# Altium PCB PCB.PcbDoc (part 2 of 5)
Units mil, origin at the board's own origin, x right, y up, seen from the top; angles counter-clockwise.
Board outline 6700 x 6500 mil, 2 copper layers (Top Layer, Bottom Layer); 203 components, 278 nets, 1296 pads, 461 vias.
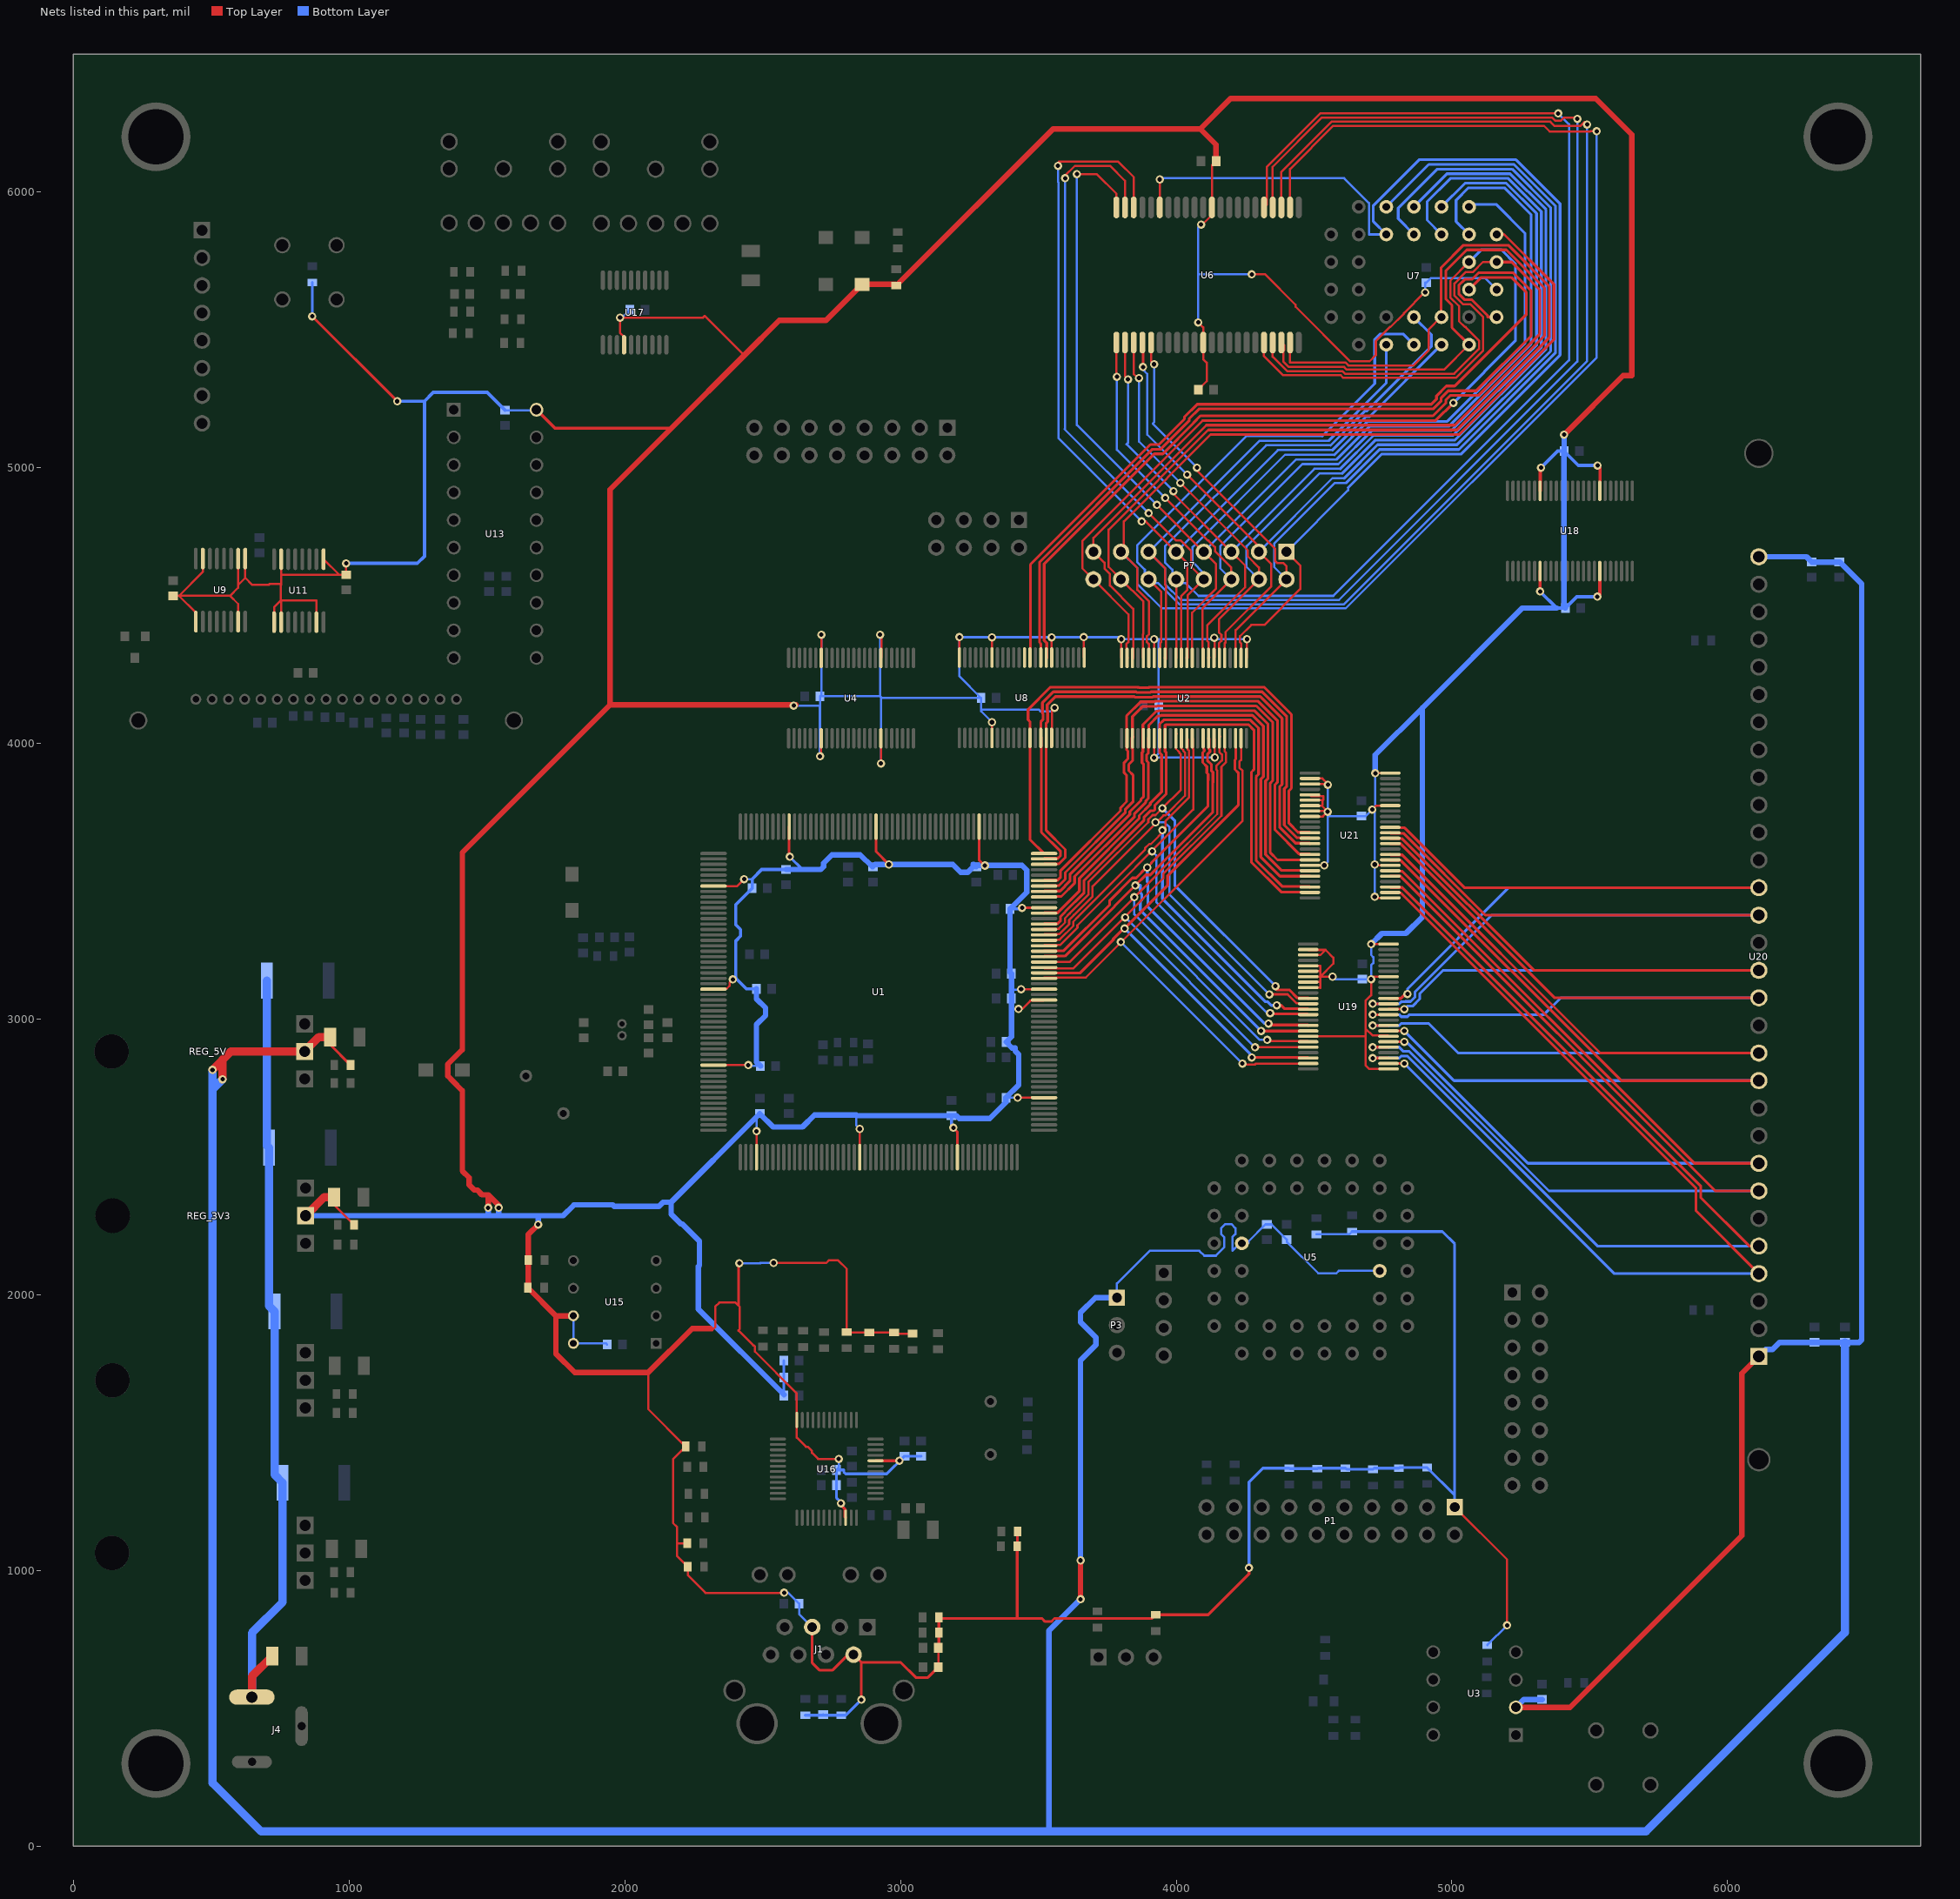
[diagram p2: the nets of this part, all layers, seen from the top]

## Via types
v1: diameter 30, hole 16, Top Layer to Bottom Layer, 461 vias

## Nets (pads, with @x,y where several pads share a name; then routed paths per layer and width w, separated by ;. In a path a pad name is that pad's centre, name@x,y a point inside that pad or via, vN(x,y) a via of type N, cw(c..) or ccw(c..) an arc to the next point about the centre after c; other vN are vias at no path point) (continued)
3V3: C1.1 C2.1 C3.1 C4.1 C6.1 C8.1 C10.1 C12.1 C14.1 C16.1 C18.1 C20.1 C21.1 C24.1 C25.1 C33.1 C34.1 C36.1 C37.1 C38.1 C49.1 C50.1 C51.1 C52.1 C67.1 C68.1 C69.1 C70.1 C76.2 C81.1 C82.1 C85.1 C86.1 C87.1 C88.1 C89.1 C90.1 C91.1 C92.1 C93.1 J1.2 J1.5 L1.2 P1.1 R3.2 R5.2 R7.2 R8.2 R9.2 R10.2 R11.2 R12.2 R15.2 R16.2 R17.2 R18.1 R22.1 R23.1 R27.2 R28.1 R29.1 R30.2 R34.2 R41.2 R42.2 R43.2 R44.2 R45.2 R46.2 R51.2 R59.2 R63.2 REG_3V3.2 U1.7 U1.26 U1.40 U1.56 U1.75 U1.93 U1.111 U1.129 U1.131 U1.146 U1.164 U1.183 U1.199 U2.1 U2.7 U2.18 U2.24 U2.31 U2.42 U4.7 U4.18 U4.31 U4.42 U6.11 U6.33 U7.32 U8.1 U8.7 U8.18 U8.24 U8.31 U8.42 U9.1 U9.2 U9.7 U9.9 U9.15 U11.1 U11.2 U11.7 U11.9 U11.15 U13.20 U15.7 U15.8 U16.22 U16.32 U16.48 U17.14 U18.7 U18.18 U18.31 U18.42 U19.1 U19.7 U19.18 U19.24 U19.26 U19.27 U19.29 U19.30 U19.31 U19.32 U19.33 U19.42 U21.1 U21.7 U21.18 U21.24 U21.26 U21.27 U21.29 U21.30 U21.31 U21.32 U21.33 U21.42 | length 49063.6
  Top Layer w8: C10.1@362,4535.44 383.44,4535.44 ; U9.9@444.43,4441.83 444.43,4474.45 383.44,4535.44 ; U9.7@470.02,4670.17 470.02,4622.02 383.44,4535.44 ; U9.15@597.98,4441.83 597.98,4505.91 568.44,4535.44 ; U9.2@597.98,4670.17 597.98,4575 ; U9.1@623.57,4670.17 623.57,4600.59 ; U11.1@728.43,4439.83 728.43,4493.41 754.02,4519 ; U11.2@754.02,4439.83 754.02,4519 ; U11.15@754.02,4668.17 754.02,4611.98 ; U11.7@881.98,4439.83 881.98,4519 754.02,4519 ; U11.9@907.57,4668.17 964.18,4611.56 ; C76.2@945.85,2354 945.85,2326.68 R51.2@1018.53,2254 ; v1(990,4653) C16.1@990,4611.56 964.18,4611.56 ; R17.2@1648.47,2026 R17.2@1650.47,2028 ; U17.14@1997.59,5445.75 1997.59,5474.41 1983,5489 v1(1983,5544) 2283.88,5544 2290.44,5550.56 2433.5,5407.5 ; 2085,1718 2085,1585.94 R59.2@2220.94,1450 2175,1404.06 2175,1172.53 2190,1157.53 2190,1098 ; R18.1@2226.47,1099 2191,1099 2190,1098 ; 2311,1877.53 2317,1871.53 2328,1882.53 2328,1956.77 2343.23,1972 2401.77,1972 2413,1960.77 ; U1.40@2321.77,2833.07 v1(2447.93,2833.07) ; U1.26@2321.77,3108.66 2324.55,3111.44 2371.1,3111.44 2381,3121.34 2381,3133 v1(2392,3144) ; U1.7@2321.77,3482.68 2407.68,3482.68 v1(2433,3508) ; v1(2416,2115) 2413,2112 2413,1960.77 ; U1.56@2478.27,2499.41 v1(2478.27,2593.73) ; v1(2540,2116) 2731.02,2116 2740.02,2125 2773.98,2125 2805,2093.98 R27.2@2805,1865.53 2807,1863.53 R34.2@2887,1863.53 R30.2@2977,1863.53 2981,1859.53 R23.1@3044,1859.53 ; v1(2578,920) 2577,919 2293,919 2228.47,983.53 R22.1@2228.47,1014 2190,1052.47 2190,1098 ; v1@2612,4138 v1(2613,4137) ; v1(2708,3953) 2708.12,3953 2712.52,3957.4 U4.31@2712.52,4018.66 ; U4.18@2712.52,4310 2713,4310.48 v1(2713,4394) ; v1(2776,1405) 2701.23,1405 2679,1427.23 2679,1433.77 2663.77,1449 2657.23,1449 2624.2,1482.03 U16.48@2624.2,1546 2624.2,1642.22 2472.28,1794.14 2472.28,1812.24 2467.78,1816.75 2466.3,1816.75 2413,1870.05 2413,1871.53 2417,1875.53 2417,1956.77 2413,1960.77 ; U1.75@2852.28,2499.41 v1(2852.28,2601.72) ; v1(2926,4394) 2931.83,4388.17 2931.83,4312.78 U4.7@2929.06,4310 ; v1(2929.06,3927.06) U4.42@2929.06,4018.66 ; C86.1@3137.56,650 C81.1@3137.56,720 ; U8.24@3213.78,4311.34 v1(3213.78,4385.22) ; U8.31@3331.89,4020 v1(3331.89,4076.89) ; U8.18@3331.89,4311.34 v1(3331.89,4385.11) ; v1(3424.96,2714.96) U1.111@3520.59,2714.96 ; v1(3428,3037) 3441.75,3037 3471.27,3066.51 3517.81,3066.51 U1.129@3520.59,3069.29 ; v1(3437.66,3108.66) U1.131@3520.59,3108.66 ; U8.42@3548.43,4020 3550,4021.58 3550,4120 v1(3559,4129) ; U8.7@3548.43,4311.34 v1(3548.43,4384.58) ; v1(3664.78,4385.22) 3664.78,4313.09 U8.1@3666.54,4311.34 ; v1(3801,4378) 3801,4311.21 U2.24@3802.21,4310 ; v1(3920,3948) 3920,4018.35 U2.31@3920.32,4018.66 ; v1(3920,4378) 3920,4310.32 U2.18@3920.32,4310 ; v1(4080,5527) 4098,5509 U6.11@4098,5454 4098,5393.77 4111,5380.77 4111,5313.56 C24.1@4080.44,5283 ; v1(4090,5882) 4095.33,5882 4129.5,5916.16 U6.33@4129.5,5944.08 4129.5,6096.94 C3.1@4144.56,6112 ; U2.42@4136.85,4018.66 4139.63,4015.88 4139.63,3948.63 v1(4140,3949) ; U2.7@4136.85,4310 4139.63,4312.78 4139.63,4381.37 v1(4138,4383) ; U2.1@4254.96,4310 4257,4312.04 v1(4257,4378) ; v1(4274,5701) 4323,5701 4433,5591 4433,5583.79 4630.79,5386 4701.21,5386 4724,5408.79 4724,5458.91 4775.09,5510 4776.91,5510 4826,5559.09 4826,5560.91 4901.18,5636.09 v1(4903,5636.09) ; U19.42@4478.66,2937.52 4686.08,2937.52 4686.6,2937 ; U19.33@4478.66,3114.69 4522.23,3114.69 4523.58,3113.34 4523.58,3135 ; U19.32@4478.66,3134.37 4522.95,3134.37 4523.58,3135 ; U19.31@4478.66,3154.06 4521.52,3154.06 ; U19.30@4478.66,3173.74 4522.32,3173.74 4523.58,3175 ; U19.29@4478.66,3193.43 4523.58,3193.43 4523.58,3175 ; U19.27@4478.66,3232.8 4523.56,3232.8 4541.77,3251 ; U19.26@4478.66,3252.48 4480.14,3251 4541.77,3251 ; U21.42@4485,3557.84 v1(4537.17,3557.84) ; U21.33@4485,3735 4532.12,3735 v1(4549.56,3752.44) v1@4547.32,3754.69 ; U21.32@4485,3754.69 v1@4547.32,3754.69 ; U21.31@4485,3774.37 4527.63,3774.37 ; U21.30@4485,3794.06 4530.95,3794.06 ; U21.29@4485,3813.74 4489.63,3809.11 4533.26,3809.11 4533.26,3796.37 4530.95,3794.06 ; U21.27@4485,3853.11 v1@4549.89,3853.11 ; U21.26@4485,3872.8 4530.21,3872.8 v1@4549.89,3853.11 ; v1(4549.89,3850.11) v1@4549.89,3853.11 ; v1(4566.95,3154.06) 4523.58,3154.06 ; v1(4706.88,3271.88) 4707.17,3272.17 U19.24@4770,3272.17 ; v1(4711,3760) 4725.37,3774.37 U21.18@4776.34,3774.37 ; v1(4720,3444) 4724.28,3439.73 U21.1@4776.34,3439.73 ; v1(4720,3561) 4723.17,3557.84 U21.7@4776.34,3557.84 ; v1(4722,3892) 4722.48,3892.48 U21.24@4776.34,3892.48 ; U19.1@4770,2819.41 4700.59,2819.41 4686.6,2833.4 4686.6,2937 ; U19.7@4770,2937.52 4767.22,2940.3 4712.42,2940.3 4686.6,2966.12 ; U19.18@4770,3154.06 4716.06,3154.06 v1(4706.88,3144.88) 4706.88,3086.68 4686.6,3066.4 4686.6,2966.12 ; P1.1@5010,1230 5200,1040 v1(5200,801.53) ; 383.44,4535.44 568.44,4535.44 ; 568.44,4535.44 597.98,4564.98 597.98,4575 ; 597.98,4575 623.57,4600.59 ; 623.57,4600.59 648.16,4576 709.23,4576 711.23,4578 752.02,4578 754.02,4576 ; 754.02,4519 752,4521.02 752,4573.98 754.02,4576 ; 754.02,4576 754.02,4611.98 ; 754.02,4611.98 754.44,4611.56 964.18,4611.56 ; 4521.52,3154.06 4523.58,3152 ; 4521.52,3154.06 4522.82,3154.06 ; 4522.82,3154.06 4523.58,3154.81 ; 4522.82,3154.06 4523.58,3154.06 ; 4523.58,3135 4523.58,3152 ; 4523.58,3152 4523.58,3154.06 ; 4523.58,3154.06 4523.58,3154.81 ; 4523.58,3154.81 4523.58,3175 ; 4523.58,3154.81 4570,3201.23 4570,3222.77 4541.77,3251 ; 4527.63,3774.37 v1@4547.32,3754.69 ; 4527.63,3774.37 4530.95,3777.69 4530.95,3794.06 ; 4686.6,2937 4686.6,2966.12
  Top Layer w10: v1(867,5549) v1(1175,5241) ; U1.199@2596.38,3698.23 2596.38,3588.62 v1(2598.63,3588.62) ; J1.5@2680,795 2680,665 2706,639 2754,639 2810,695 J1.2@2830,695 2858,667 ; v1(2784,1244) 2784,1237.89 2798.61,1223.28 2798.61,1194.43 U16.22@2801.37,1191.67 ; v1(2858,532) 2858,667 ; U16.32@2909.64,1398.36 v1(2996.36,1398.36) ; U1.183@2911.34,3698.23 2911.34,3607.66 v1(2958,3561) ; C86.1@3137.56,650 3099.56,612 3056,612 3001,667 2858,667 ; C81.1@3137.56,720 3139.53,721.97 R41.2@3139.53,775 R42.2@3139.53,826.22 ; R42.2@3139.53,830 R42.2@3139.53,826.22 ; v1(3192,2606) 3206.61,2591.39 U1.93@3206.61,2499.41 ; U1.164@3285.35,3698.23 3285.35,3576.65 3305,3557 v1(3306,3557) ; R28.1@3424.53,1142 3424.53,1089 R29.1@3423.53,1088 3423.53,826.69 3424,826.22 ; v1(3440.94,3403.94) U1.146@3520.59,3403.94 ; v1(4264,1010) 4264,988 4116,840 R5.2@3926,840 3912.22,826.22 3558.4,826.22 3547.18,815 3524.82,815 3513.6,826.22 3424,826.22 ; R42.2@3139.53,826.22 3424,826.22
  Top Layer w12: U13.20@1680,5210 1747,5143 2169,5143 ; v1(5319.69,4551.32) U18.31@5319.69,4625 ; U18.18@5319.69,4916.34 5320.46,4917.12 5320.46,4997.46 v1(5323,5000) ; v1(5527,4532) 5536.22,4541.22 U18.42@5536.22,4625 ; v1(5528,5008) 5537,4999 5537,4917.12 U18.7@5536.22,4916.34
  Top Layer w20: v1(1505,2316) 1505,2363 ; v1(1543,2316) 1543,2325 1505,2363 ; R17.2@1648.47,2026 1750.47,1924 ; R17.2@1650.47,2028 R16.2@1650.47,2126 1650.47,2219.47 v1(1686,2255) ; U15.7@1814,1924 1750.47,1924 ; 2311,1877.53 2244.53,1877.53 2085,1718 1819,1718 1750.47,1786.53 1750.47,1924 ; v1@2621,4140 1947,4140 ; C3.1@4144.56,6112 4144.56,6171.7 4087.25,6229 ; v1(5407,5120) 5621,5334 5652,5334 5652,6208 5521,6339 4197.25,6339 4087.25,6229 ; 1505,2363 1482.25,2363 1465.25,2380 1454.12,2380 1435.19,2398.93 1435.19,2425.44 1411,2449.62 1411,2740.82 1377.44,2774.38 1377.33,2774.38 1358,2793.71 1358,2836.29 1410.89,2889.18 1411,2889.18 1411,3604 1947,4140 ; 1947,4140 1947,4921 2169,5143 2433.5,5407.5 2560,5534 2729.94,5534 L1.2@2860.94,5665 2980.47,5665 R63.2@2985,5660.47 3553.53,6229 4087.25,6229
  Top Layer w30: REG_3V3.2@843,2287 910,2354 C76.2@945.85,2354
  Bottom Layer w8: C21.1@1566,5208.56 1678.56,5208.56 U13.20@1680,5210 ; 1697,2287 1699,2289 ; U15.7@1814,1924 U15.8@1814,1824 1932.44,1824 C2.1@1936.44,1820 ; v1(1983,5544) 1990.44,5544 C1.1@2018.44,5572 ; v1(2392,3144) 2407.4,3144 2410,3141.4 ; v1(2416,2115) 2492,2115 2491,2116 v1(2540,2116) ; v1(2433,3508) 2462.4,3508 2462.44,3508.04 ; v1(2447.93,2833.07) 2451,2830 C67.1@2492.44,2830 ; v1(2478.27,2593.73) 2478.27,2645.71 C51.1@2490,2657.44 ; v1(2578,920) 2592.56,920 C85.1@2632.56,880 2632.56,842.44 J1.5@2680,795 ; v1(2613,4137) 2708.56,4137 ; v1(2708,3953) 2708,4136.44 2708.56,4137 ; v1(2713,4394) 2713,4175.44 C20.1@2708.56,4171 ; C89.1@2767.56,1365 2776,1373.44 v1(2776,1405) ; 2840,2652.44 2840,2614 v1(2852.28,2601.72) ; v1(2926,4394) 2926,4171 ; v1(2929.06,3927.06) 2929.06,4167.95 ; v1@3331,4386 v1@3331.78,4385.22 ; v1(3331.89,4076.89) 3292.44,4116.34 ; v1(3331.89,4385.11) v1@3331.78,4385.22 ; C34.1@3382.56,2715 C34.1@3382.56,2715 v1(3424.96,2714.96) ; 3402.56,3036 3427,3036 v1(3428,3037) ; 3402.56,3107 3436,3107 v1(3437.66,3108.66) ; v1@3548,4385 v1(3548.43,4384.58) ; v1(3559,4129) 3546.34,4116.34 3507.43,4116.34 3500.77,4123 3299.1,4123 3292.44,4116.34 ; v1(3920,3948) v1@3921,3949 ; v1(4080,5527) 4080,5701 ; v1(4090,5882) 4080,5872 4080,5701 ; v1(4138,4383) v1@4133,4378 ; v1(4140,3949) v1@3921,3949 ; v1(4257,4378) v1@4133,4378 ; v1(4274,5701) 4080,5701 ; R46.2@4509,2219.47 4628,2219.47 R45.2@4638,2229.47 ; v1(4537.17,3557.84) 4549.56,3570.23 4549.56,3736.44 ; v1(4549.89,3850.11) 4549.89,3752.77 v1(4549.56,3752.44) 4549.56,3736.44 ; v1(4566.95,3154.06) 4576.12,3144.88 C33.1@4675,3144.88 v1(4706.88,3144.88) 4706.88,3195.11 4715,3203.23 4715,3224.77 4706.88,3232.89 v1(4706.88,3271.88) ; v1(4720,3444) v1(4720,3561) 4720,3751 v1(4711,3760) ; v1(4722,3892) 4722,3771 v1(4711,3760) ; v1(4903,5636.09) 4903,5671 4903.12,5670.88 C12.1@4907,5670.88 4924.12,5688 5120,5688 U7.32@5162,5646 ; R3.2@5128,729.53 v1(5200,801.53) ; 2708.56,4137 C20.1@2708.56,4171 ; C20.1@2708.56,4171 2926,4171 ; 2926,4171 2929.06,4167.95 ; 2929.06,4167.95 2932,4165 C6.1@3292.44,4165 ; 3292.44,4116.34 C6.1@3292.44,4165 ; C6.1@3292.44,4165 3213.78,4243.66 v1(3213.78,4385.22) v1@3331.78,4385.22 ; v1@3331.78,4385.22 v1(3664.78,4385.22) 3793.78,4385.22 v1(3801,4378) v1(3920,4378) 3936,4378 ; v1@3921,3949 3936.56,3964.56 C38.1@3936.56,4138 3936.56,4377.44 3936,4378 ; 3936,4378 v1@4133,4378 ; 4549.56,3736.44 C18.1@4672,3736.44 4687.44,3736.44 v1(4711,3760)
  Bottom Layer w10: v1(867,5549) R15.2@867,5671.47 ; v1(1175,5241) 1274,5241 ; C87.1@2577.44,1635 2580,1635 2578.72,1636.28 2577.44,1637.56 C88.1@2577.44,1700 C91.1@2577.44,1762 ; v1(2598.63,3588.62) 2644.25,3543 2644.69,3542.56 ; R44.2@2655,475.47 2718.03,475.47 C82.1@2720,477.44 2721.97,475.47 R43.2@2785,475.47 2801.47,475.47 v1(2858,532) ; v1(2784,1244) 2784,1248.18 2767.56,1264.62 C90.1@2767.56,1310 C89.1@2767.56,1365 2794.28,1365 2794.28,1357.72 2801.31,1350.69 2950.69,1350.69 C93.1@3014.88,1414.88 ; v1@2958,3559 v1(2958,3561) ; v1(2996.36,1398.36) 3012.88,1414.88 C93.1@3014.88,1414.88 ; C93.1@3015,1414.88 C93.1@3014.88,1414.88 ; C92.1@3075,1414.88 3074.88,1415 3015,1415 C93.1@3014.88,1414.88 ; C25.1@3185,2649.88 3185,2613 v1(3192,2606) ; C8.1@3397.56,3400 3437,3400 v1(3440.94,3403.94) ; v1(4264,1010) 4264,1321 4314.53,1371.53 R7.2@4410,1371.53 4412,1369.53 R8.2@4512,1369.53 4514,1371.53 R9.2@4614,1371.53 4618,1367.53 R10.2@4714,1367.53 4718,1371.53 R11.2@4808,1371.53 4810,1373.53 R12.2@4910,1373.53 5010,1273.53 ; R45.2@4638,2229.47 4965.53,2229.47 5010,2185 5010,1273.53 ; P1.1@5010,1230 5010,1273.53
  Bottom Layer w12: v1(990,4653) 1248,4653 1274,4679 1274,5241 1306,5273 1501.56,5273 C21.1@1566,5208.56 ; 2407.4,3144 2403,3148.4 2403,3284.4 2420,3301.4 2420,3324.6 2403,3341.6 2403,3415.56 C68.1@2462.44,3475 2462.44,3508.04 2496.96,3542.56 C69.1@2585,3542.56 ; 2410,3141.4 2441.4,3110 C52.1@2477.44,3110 ; v1(5319.69,4551.32) 5380,4491 C14.1@5411.44,4491 5452.44,4532 v1(5527,4532) ; v1(5323,5000) 5383,5060 C50.1@5406.44,5060 5458.44,5008 v1(5528,5008)
  Bottom Layer w20: REG_3V3.2@843,2287 1505,2287 ; v1(1505,2316) 1505,2287 ; v1(1543,2316) 1543,2287 ; v1(1686,2255) 1686,2287 ; C52.1@2477.44,3110 2477.44,3073.81 2511,3040.25 2511,3013.75 2477.44,2980.19 2477.44,2845 C67.1@2492.44,2830 ; C51.1@2478.27,2645.71 2168.56,2336 ; C51.1@2490,2657.44 2538.44,2609 2645,2609 2688.44,2652.44 2705.3,2652.44 2705.75,2652 2839.56,2652 2840,2652.44 2842.56,2649.88 C25.1@3185,2649.88 3202.46,2649.88 3213.05,2639.3 3324.3,2639.3 3382.56,2697.56 C34.1@3382.56,2715 3429,2761.44 3429,2871.56 3416.31,2884.25 3416.31,2895.72 3404.84,2895.72 C37.1@3383.56,2917 3402.56,2936 3402.56,3036 C4.1@3402.56,3075 3402.56,3107 C36.1@3402.56,3165 3397.56,3170 C8.1@3397.56,3400 3458,3460.44 3458,3540 3440.28,3557.72 3275,3557.72 C49.1@3275,3552.56 3266.56,3561 3263,3561 3263,3551.75 3244.25,3533 3217.75,3533 3189.75,3561 v1(2958,3561) 2908.44,3561 C70.1@2900,3552.56 2897.61,3552.56 2854.17,3596 2751.75,3596 2721,3565.25 2721,3553 2710.56,3542.56 2644.69,3542.56 ; C87.1@2577.44,1637.56 2271.06,1943.94 2267,1948 2267,2103.25 2271.06,2107.31 2271.06,2195.23 2208.97,2257.31 2204.38,2257.31 2168.56,2293.14 2168.56,2336 ; C69.1@2585,3542.56 2585.44,3543 2644.25,3543 ; v1(4706.88,3271.88) 4746,3311 4833,3311 4893,3371 4893,4129 ; v1(4722,3892) 4722,3958 4893,4129 ; 5380,4491 5255,4491 4893,4129 ; v1(5407,5120) 5407,5060.56 C50.1@5406.44,5060 5406.44,4496 C14.1@5411.44,4491 ; 1505,2287 1543,2287 ; 1543,2287 1686,2287 ; 1686,2287 1697,2287 1777,2287 1816.33,2326.33 1956.25,2326.33 1961.58,2321 2124.18,2321 2139.18,2336 2168.56,2336
5V: C32.1 C56.1 C57.1 C74.2 C75.1 C77.1 C83.1 C84.1 P3.1 R49.2 REG_5V.2 U3.2 U5.12 U5.34 U20.1 U20.30 | length 19589
  Top Layer w10: C74.2@931.85,2935 931.85,2907.68 R49.2@1005.53,2834
  Top Layer w20: v1(3653,896) v1(3653,1037) ; U3.2@5232,504 5428,504 6051,1127 6051,1715 U20.1@6113,1777
  Top Layer w30: v1(505,2816) 572,2883 REG_5V.2@839,2883 891,2935 C74.2@931.85,2935 ; v1(542,2782) 542,2845
  Bottom Layer w8: P3.1@3785,1990 3785,2041 3904,2160 4084.21,2160 4102.21,2142 4143.91,2142 4174,2172.09 4174,2209.23 4163,2220.23 4163,2241.77 4178.23,2257 4199.77,2257 4215,2241.77 4215,2220.23 4204,2209.23 4204,2160 4231,2187 U5.34@4238,2187 4260.44,2187 4263,2189.56 4263,2194.77 4323.79,2255.56 C57.1@4329,2255.56 4345.88,2255.56 C56.1@4401,2200.44 4401,2192.23 4515.23,2078 4580.77,2078 4589.77,2087 U5.12@4738,2087
  Bottom Layer w20: 3539,54 3539,782 v1(3653,896) ; v1(3653,1037) 3653,1762.75 3709,1818.75 3709,1845.25 3653,1901.25 3653,1936 3707,1990 P3.1@3785,1990 ; U3.2@5232,504 5260.44,532.44 C32.1@5327,532.44 ; U20.1@6113,1777 6138,1802 6162.56,1802 6188,1827.44 C84.1@6315,1827.44 C77.1@6425,1827.44 6476.44,1827.44 6486,1837 6486,4578.95 6407.39,4657.56 C75.1@6405,4657.56 C83.1@6305,4657.56 6285.56,4677 U20.30@6113,4677
  Bottom Layer w30: v1(505,2816) 505,2745 ; v1(542,2782) 505,2745 ; C77.1@6425,1827.44 6425,775 5704,54 3539,54 681,54 505,230 505,2745
12V: C71.2 J4.VCC R58.1 R60.2 R61.2 R62.2 | length 2848.1
  Top Layer w30: J4.VCC@648,541 648,616.15 C71.2@721.85,690
  Bottom Layer w30: J4.VCC@648,541 648,774 758.8,884.8 R58.1@758.8,1319 729.8,1348 R62.2@729.8,1940 709.8,1960 R61.2@709.8,2534 701.8,2542 R60.2@701.8,3140
A_3V3_BUF_0: P7.1 U2.2 U6.39 U7.12 | length 4380.6
  Top Layer w8: U6.39@3940.52,5944.08 v1(3940.52,6045.52) ; U2.2@4235.28,4310 4235.28,4362.96 4231,4367.23 4231,4388.77 4272.23,4430 4320,4430 4450,4560 4450,4645 P7.1@4400,4695
  Bottom Layer w8: v1(3940.52,6045.52) 3945,6050 4608.91,6050 4699,5959.91 4699,5846 U7.12@4762,5846 ; P7.1@4400,4695 4623.42,4918.42 4623.42,4928
  Bottom Layer w10: 4623.42,4928 4744.42,5049 5032.29,5049 5392,5408.71 5392,5957.25 5232.25,6117 4880.67,6117 4715,5951.33 4715,5893 U7.12@4762,5846
A_3V3_BUF_1: P7.2 U2.3 U6.5 U7.11 | length 4168.6
  Top Layer w8: U6.5@3909.02,5454 3909.02,5385.98 v1(3920,5375) ; v1(4075,5000) 4075,4990 4359.47,4705.53 4359.47,4660.92 4365.92,4654.47 4387.94,4654.47 4400,4642.42 P7.2@4400,4595 4215.59,4410.59 U2.3@4215.59,4310
  Bottom Layer w8: v1(3920,5375) 3920,5165 3915,5160 v1(4075,5000) ; P7.2@4400,4595 4355,4640 4355,4724.61 4575.39,4945 4616.37,4945
  Bottom Layer w10: 4616.37,4945 4737.37,5066 5025.25,5066 5375,5415.75 5375,5950.21 5225.21,6100 4916,6100 U7.11@4762,5946
A_3V3_BUF_2: P7.3 U2.5 U6.4 U7.10 | length 4075.9
  Top Layer w8: U6.4@3877.53,5454 3880,5451.53 v1(3880,5365) ; v1(4040,4975) 4300,4715 P7.3@4300,4695 4345,4650 4345,4570 4179,4404 4179,4366.02 4176.22,4363.24 U2.5@4176.22,4310
  Bottom Layer w8: v1(3880,5365) 3880,5355 3895,5340 3895,5120 v1(4040,4975) ; P7.3@4300,4695 4567,4962 4609.33,4962
  Bottom Layer w10: 4609.33,4962 4730.33,5083 5018.21,5083 5358,5422.79 5358,5943.17 5218.17,6083 4946.67,6083 4805,5941.33 4805,5903 U7.10@4862,5846
A_3V3_BUF_3: P7.4 U2.6 U6.3 U7.9 | length 4019.7
  Top Layer w8: U6.3@3846.03,5454 3846.03,5338.97 3865,5320 v1(3865,5325) ; v1(4015,4945) 4259.47,4700.53 4259.47,4678.21 4300,4637.69 P7.4@4300,4595 4155,4450 4155,4402.77 4164,4393.77 4164,4372.23 4155,4363.23 4155,4311.54 U2.6@4156.54,4310
  Bottom Layer w8: v1(3865,5325) 3865,5095 v1(4015,4945) ; P7.4@4300,4595 4255,4640 4255,4715 4519,4979 4602.29,4979
  Bottom Layer w10: 4602.29,4979 4723.29,5100 5011.17,5100 5341,5429.83 5341,5936.12 5211.12,6066 4981.96,6066 U7.9@4862,5946
A_3V3_BUF_4: P7.5 U2.8 U6.2 U7.8 | length 3952.8
  Top Layer w8: U6.2@3814.54,5454 3814.54,5330.46 v1(3825,5320) ; v1(3990,4915) 3990,4905 P7.5@4200,4695 4250,4645 4250,4566.21 4112,4428.21 4112,4372.23 4117.17,4367.07 U2.8@4117.17,4310
  Top Layer w10: U2.8@4117.17,4310 U2.8@4118.94,4311.78
  Bottom Layer w8: v1(3825,5320) 3825,5090 3820,5085 v1(3990,4915) ; P7.5@4200,4695 4501,4996 4595.25,4996
  Bottom Layer w10: 4595.25,4996 4716.25,5117 5004.12,5117 5324,5436.88 5324,5929.08 5204.08,6049 4994,6049 4910,5965 4910,5898 U7.8@4962,5846
A_3V3_BUF_5: P7.6 U2.9 U6.1 U7.7 | length 3852.2
  Top Layer w8: U6.1@3783.04,5454 3783.04,5331.96 v1(3785,5330) ; v1(3960,4890) 4114.47,4735.53 4116.79,4735.53 4140.53,4711.79 4140.53,4697.16 4200,4637.69 P7.6@4200,4595 4095.7,4490.7 4095.7,4311.78 U2.9@4097.48,4310
  Bottom Layer w8: v1(3785,5330) 3785,5065 v1(3960,4890) ; P7.6@4200,4595 4160,4635 4160,4677.16 4159.47,4677.69 4159.47,4714.47 4458,5013 4588.21,5013
  Bottom Layer w10: 4588.21,5013 4709.21,5134 4997.08,5134 5307,5443.92 5307,5922.04 5197.04,6032 5048,6032 U7.7@4962,5946
A_3V3_BUF_6: P7.7 U2.11 U6.44 U7.6 | length 4665.5
  Top Layer w8: v1(3640,6065) 3711.63,6065 3783.04,5993.59 U6.44@3783.04,5944.08 ; v1(3930,4865) P7.7@4100,4695 4145,4650 4145,4561.21 4058.11,4474.32 U2.11@4058.11,4310
  Bottom Layer w8: v1(3640,6065) 3640,5155 v1(3930,4865) ; P7.7@4100,4695 4435,5030 4581.17,5030
  Bottom Layer w10: 4581.17,5030 4702.17,5151 4990.04,5151 5287,5447.96 5287,5918 5190,6015 5060,6015 5015,5970 5015,5893 U7.6@5062,5846
A_3V3_BUF_7: P7.8 U2.12 U6.43 U7.5 | length 4646.6
  Top Layer w8: v1(3597,6050) 3597,6054.77 3595,6056.77 3633.23,6095 3760,6095 3814.54,6040.46 U6.43@3814.54,5944.08 ; v1(3900,4835) 3999.47,4735.53 4016.79,4735.53 4055,4697.31 4055,4640 P7.8@4100,4595 4041.2,4536.2 4041.2,4310 U2.12@4038.43,4310
  Top Layer w10: U2.12@4038.43,4310 U2.12@4040,4311.58
  Bottom Layer w8: v1(3597,6050) 3597,5142 3595,5140 v1(3900,4835) ; P7.8@4100,4595 4100,4617.16 4059.47,4657.69 4059.47,4711.79 4394.69,5047 4574.12,5047
  Bottom Layer w10: 4574.12,5047 4695.12,5168 4983,5168 5265,5450 5265,5850 5160,5955 5071,5955 U7.5@5062,5946
A_3V3_BUF_8: P7.9 U2.13 U6.42 U7.27 | length 3691.2
  Top Layer w8: v1(3571,6095) 3571,6106 3575,6110 3790,6110 3846.03,6053.97 U6.42@3846.03,5944.08 ; v1(3875,4805) 3890,4805 P7.9@4000,4695 4040,4655 4040,4633.79 4040.53,4633.26 4040.53,4556.74 4018.74,4534.95 U2.13@4018.74,4310
  Bottom Layer w8: v1(3571,6095) 3571,6036.77 3573,6034.77 3573,5107 v1(3875,4805) ; P7.9@4000,4695 4369,5064 4567.08,5064
  Bottom Layer w10: 4567.08,5064 4688.08,5185 4701,5185 U7.27@4962,5446
A_3V3_BUF_9: P7.10 U2.14 U6.27 U7.26 | length 5830.5
  Top Layer w8: U2.14@3999.06,4310 4000,4310.95 P7.10@4000,4595 ; U6.27@4318.47,5944.08 4328.14,5953.75 4328.14,6090.57 4522.57,6285 v1(5385,6285)
  Bottom Layer w8: 4560.04,5081 4326,5081 3959.47,4714.47 3959.47,4656.74 3986.34,4629.87 3986.34,4617.44 3981.95,4613.05 P7.10@4000,4595 4018.05,4576.95 4022.44,4581.34 4034.87,4581.34 4081.21,4535 4570,4535 5425,5390 5425,6245 v1(5385,6285)
  Bottom Layer w10: 4560.04,5081 4684.04,5205 4690,5205 4925,5440 4925,5483 U7.26@4862,5546
A_3V3_BUF_10: P7.11 U2.16 U6.26 U7.23 | length 5913.7
  Top Layer w8: P7.11@3900,4695 3959.47,4635.53 3959.47,4575.22 3962.46,4572.23 3962.46,4305 3959.69,4307.78 U2.16@3959.69,4310 ; U6.26@4349.97,5944.08 4349.97,6091.18 4528.79,6270 5363.23,6270 5374.23,6259 5395.77,6259 5406.77,6270 5450,6270 v1(5455,6265)
  Top Layer w10: U2.16@3959.69,4310 U2.16@3960,4310.32
  Bottom Layer w8: 4553,5098 4303,5098 P7.11@3900,4695 3959.47,4635.53 3959.47,4578.21 4017.69,4520 4590,4520 5455,5385 v1(5455,6265)
  Bottom Layer w10: 4553,5098 4762,5307 U7.23@4762,5446
A_3V3_BUF_11: P7.12 U2.17 U6.25 U7.25 | length 6065
  Top Layer w8: P7.12@3900,4595 3946,4549 3946,4367.23 3942.78,4364.01 3942.78,4312.78 U2.17@3940,4310 ; U6.25@4381.46,5944.08 4381.46,6072.68 4563.79,6255 5357.02,6255 5373.02,6239 5465.77,6239 5480.88,6254.12 v1(5490,6245)
  Bottom Layer w8: 4530,5115 4255,5115 3859.47,4719.47 3859.47,4656.74 3886.34,4629.87 3886.34,4617.44 3881.95,4613.05 P7.12@3900,4595 3918.05,4576.95 3922.44,4581.34 3934.87,4581.34 4011.21,4505 4608.79,4505 5490,5386.21 v1(5490,6245)
  Bottom Layer w10: 4530,5115 4720,5305 4720,5465 4740,5485 4823,5485 U7.25@4862,5446
A_3V3_BUF_12: P7.13 U2.19 U6.24 U7.4 | length 7234.3
  Top Layer w8: P7.13@3800,4695 P7.13@3810,4685 ; U2.19@3900.63,4310 3900.63,4360.6 3894,4367.23 3894,4388.77 3900.63,4395.4 3900.63,4515.58 3859.47,4556.74 3859.47,4635.53 P7.13@3810,4685 ; 4125,5120 3810,4805 P7.13@3810,4685 ; U6.24@4412.96,5944.08 4412.96,6082.96 4570,6240 5333.79,6240 5354.79,6219 5500.77,6219 5501.77,6220 v1(5525,6220)
  Top Layer w10: 4125,5120 5025.21,5120 5370,5464.79 5370,5665.21 5189.21,5846 U7.4@5162,5846
  Bottom Layer w8: P7.13@3800,4695 3859.47,4635.53 3859.47,4578.21 3947.69,4490 4615,4490 5525,5400 v1(5525,6220)
A_3V3_BUF_13: P7.14 U2.20 U6.21 U7.28 | length 4001.3
  Top Layer w8: U2.20@3880.95,4310 3879,4311.95 3879,4394.98 3880.95,4396.93 3880.95,4514.06 P7.14@3800,4595 3755,4640 3755,4775 4117,5137 ; U6.21@4412.96,5454 4412.96,5382.04 4613.53,5382.04 4624.57,5371 4861,5371 4915,5425 4915,5501 4961,5547 U7.28@4962,5546
  Top Layer w10: 4117,5137 5018.17,5137 5353,5471.83 5353,5658.17 5204.17,5807 5042.04,5807 4961,5725.96 U7.28@4961,5547
A_3V3_BUF_14: P7.15 U2.22 U6.20 U7.29 | length 4157.6
  Top Layer w8: U2.22@3841.58,4310 3844.35,4312.78 3844.35,4487.8 3759.47,4572.69 3759.47,4614.31 3740,4633.79 3740,4655 P7.15@3700,4695 3700,4745 4109,5154 ; U6.20@4381.46,5454 4391.13,5444.33 4391.13,5427.47 4388.29,5424.63 4388.29,5385.5 4408.79,5365 4609.36,5365 4618.36,5356 4972,5356 U7.29@5062,5446
  Top Layer w10: U2.22@3841.58,4310 U2.22@3843.35,4308.22 ; 4109,5154 5011.12,5154 5336,5478.88 5336,5651.12 5197.12,5790 5053.67,5790 4978,5714.33 4978,5611.21 5000,5589.21 5000,5508 U7.29@5062,5446
A_3V3_BUF_15: P7.16 U2.23 U6.19 U7.3 | length 4108.8
  Top Layer w8: U2.23@3821.89,4310 3821.89,4343.4 3819.74,4343.4 3819.11,4344.03 3819.11,4359.34 3827,4367.23 3827,4468 P7.16@3700,4595 3660,4635 3660,4677.16 3659.47,4677.69 3659.47,4734.47 4096,5171 ; U6.19@4349.97,5454 4349.97,5402.61 4402.57,5350 4603.15,5350 4612.15,5341 5007.91,5341 5098,5431.09 5098,5460.91 5048.91,5510 5047.09,5510 5026,5531.09 5026,5585.83 4994,5617.83 4994,5678 U7.3@5062,5746
  Top Layer w10: U2.23@3821.89,4310 U2.23@3823.67,4310 ; 4096,5171 4941,5171 v1(5005,5235)
  Bottom Layer w10: v1(5005,5235) 5230,5460 5230,5740 5180,5790 5106,5790 U7.3@5062,5746
A_3V3_BUF_16: U6.18 U7.2 U8.8 | length 4259.2
  Top Layer w8: U6.18@4318.47,5454 4318.47,5404.49 4387.96,5335 4596.93,5335 4605.93,5326 5014.13,5326 5113,5424.87 5113,5545.91 5065.91,5593 5040.05,5593 5009,5624.05 5009,5667.95 5051.05,5710 5076.91,5710 5112.91,5746 U7.2@5162,5746
  Top Layer w10: U8.8@3528.74,4311.34 3529.18,4311.34 3530.52,4310 3530.52,4364.3 3521.43,4373.39 3521.43,4650.78 3920.65,5050 3951.27,5050 4064,5162.73 4064,5164 4088,5188 4931.08,5188 4978,5234.92 4978,5246.18 4993.82,5262 5095.08,5262 5319,5485.92 5319,5644.08 5217.08,5746 U7.2@5162,5746
A_3V3_BUF_17: U7.30 U8.9 | length 3160
  Top Layer w10: U8.9@3509.06,4311.34 3509.06,4361.72 3504.43,4366.35 3504.43,4657.82 3913.61,5067 3944.23,5067 4047,5169.77 4047,5177 4083,5213 4932.04,5213 4961,5241.96 4961,5253.23 4986.77,5279 5088.04,5279 5287,5477.96 5287,5642.04 5222.04,5707 5096.54,5707 5072.54,5683 5046.67,5683 5025,5661.33 5025,5630.67 5046.67,5609 5072.54,5609 5129,5552.54 5129,5546 U7.30@5162,5546
A_3V3_BUF_18: U7.1 U8.11 | length 2854.9
  Top Layer w10: U8.11@3469.69,4311.34 3471.46,4309.56 3471.46,4648.9 3906.57,5084 3937.18,5084 4030,5176.82 4030,5184.04 4075.96,5230 4925,5230 4944,5249 4944,5260.27 4979.73,5296 5009.84,5296 5270,5556.16 5270,5635 5215,5690 5106,5690 U7.1@5062,5646
A_3V3_BUF_19: U8.12
A_5V_0: U19.2 U20.4 U21.2 | length 3616.5
  Top Layer w10: U19.2@4770,2839.1 v1(4827.4,2839.1) ; U21.2@4776.34,3459.41 4778.12,3457.63 4815.25,3457.63 5885,2387.88 5885,2305 U20.4@6113,2077
  Bottom Layer w10: v1(4827.4,2839.1) 5589.5,2077 U20.4@6113,2077
A_5V_1: U19.3 U20.5 U21.3 | length 3646.6
  Top Layer w10: v1(4712.6,2858.78) U19.3@4770,2858.78 ; U21.3@4776.34,3479.1 4778.12,3477.32 4819.61,3477.32 5902,2394.92 5902,2353.43 6078.43,2177 U20.5@6113,2177
  Bottom Layer w10: v1(4712.6,2858.78) 4808.9,2858.78 4816.22,2866.1 4838.59,2866.1 5527.68,2177 U20.5@6113,2177
A_5V_2: U19.5 U20.7 U21.5 | length 3483.1
  Top Layer w10: v1(4712.6,2898.15) U19.5@4770,2898.15 ; U21.5@4776.34,3518.47 4813.47,3518.47 5954.94,2377 U20.7@6113,2377
  Bottom Layer w10: v1(4712.6,2898.15) 4808.9,2898.15 4823.96,2883.1 4845.63,2883.1 5351.72,2377 U20.7@6113,2377
A_5V_3: U19.6 U20.8 U21.6 | length 3301.8
  Top Layer w10: U19.6@4770,2917.84 v1(4827.4,2917.84) ; U21.6@4776.34,3538.15 4778.12,3536.37 4819.61,3536.37 5878.98,2477 U20.8@6113,2477
  Bottom Layer w10: v1(4827.4,2917.84) 4834.93,2917.84 5275.76,2477 U20.8@6113,2477
A_5V_4: U19.8 U20.11 U21.8 | length 3085.9
  Top Layer w10: U19.8@4770,2957.21 v1(4827.4,2957.21) ; U21.8@4776.34,3577.52 4778.12,3575.74 4815.25,3575.74 5613.99,2777 U20.11@6113,2777
  Bottom Layer w10: v1(4827.4,2957.21) 5007.61,2777 U20.11@6113,2777
A_5V_5: U19.9 U20.12 U21.9 | length 3140.2
  Top Layer w10: v1(4712.6,2976.89) U19.9@4770,2976.89 ; U21.9@4776.34,3597.21 4778.12,3595.43 4819.61,3595.43 5538.03,2877 U20.12@6113,2877
  Bottom Layer w10: v1(4712.6,2976.89) 4808.9,2976.89 4816.22,2984.21 4915.79,2984.21 5023,2877 U20.12@6113,2877
A_5V_6: U19.11 U20.14 U21.11 | length 3057.5
  Top Layer w10: v1(4712.6,3016.26) U19.11@4770,3016.26 ; U21.11@4776.34,3636.58 4813.47,3636.58 5373.05,3077 U20.14@6113,3077
  Bottom Layer w10: v1(4712.6,3016.26) 4808.9,3016.26 4816.22,3008.95 4838.59,3008.95 4845.9,3016.26 5333.74,3016.26 5394.48,3077 U20.14@6113,3077
A_5V_7: U19.12 U20.15 U21.12 | length 2947.6
  Top Layer w10: U19.12@4770,3035.95 v1(4827.4,3035.95) ; U21.12@4776.34,3656.26 4778.12,3654.48 4819.61,3654.48 5297.09,3177 U20.15@6113,3177
  Bottom Layer w10: v1(4827.4,3035.95) 4838.46,3047 4857.23,3047 4883,3072.77 4883,3091.54 4968.46,3177 U20.15@6113,3177
A_5V_8: U19.13 U20.17 U21.13 | length 3062.4
  Top Layer w10: v1(4712.6,3055.63) U19.13@4770,3055.63 ; U21.13@4776.34,3675.95 4778.12,3674.17 4823.96,3674.17 5121.13,3377 U20.17@6113,3377
  Bottom Layer w10: v1(4712.6,3055.63) 4808.9,3055.63 4816.22,3062.95 4830.36,3062.95 4831.41,3064 4850.18,3064 4866,3079.82 4866,3098.59 5144.41,3377 U20.17@6113,3377
A_5V_9: U19.14 U20.18 U21.14 | length 2947.6
  Top Layer w10: U19.14@4770,3075.32 4814.85,3075.32 4830.54,3091 v1(4839,3091) ; U21.14@4776.34,3695.63 4778.12,3693.85 4828.32,3693.85 5045.17,3477 U20.18@6113,3477
  Bottom Layer w10: v1(4839,3091) 4839,3109.77 5206.23,3477 U20.18@6113,3477
ADDR0: U1.133 U2.47 U19.47 | length 2131.8
  Top Layer w8: U1.133@3520.59,3148.03 3520.59,3150.81 3671.77,3150.81 4241,3720.05 4241,3900.23 4229,3912.23 4229,3933.77 4235.28,3940.04 U2.47@4235.28,4018.66 ; v1(3799,3280) v1@3799,3281 ; v1(4239.91,2839.1) 4244,2835 4284.77,2835 4288.86,2839.1 U19.47@4478.66,2839.1
  Bottom Layer w8: v1(3799,3280) v1(4239.91,2839.1)
ADDR1: U1.134 U2.46 U19.46 | length 2092.3
  Top Layer w10: U1.134@3520.59,3167.72 3651.9,3167.72 3772,3287.82 3772,3291.18 3809.72,3328.91 v1(3813.09,3328.91) 3969,3484.82 3969,3520 4225,3776 4225,3893.6 4213,3905.6 4213,3940.4 4215.59,3942.99 U2.46@4215.59,4018.66 ; v1(4274,2861) 4439.31,2861 4439.31,2860.56 4476.88,2860.56 U19.46@4478.66,2858.78
  Bottom Layer w10: v1(3813.09,3328.91) 4274,2868 v1(4274,2861)
ADDR2: U1.135 U2.44 U19.44 | length 2036.9
  Top Layer w8: U1.135@3520.59,3187.4 3523.37,3184.62 3627.2,3184.62 v1@3811.58,3369 ; v1@3810,3369 v1@3811.58,3369 ; v1(3815,3369) v1@3811.58,3369 ; U2.44@4176.22,4018.66 4176.22,3970.76 4181,3965.98 4181,3932.02 4164,3915.02 4164,3737.63 3953,3526.63 3953,3510.42 v1@3811.58,3369 ; v1(4285.85,2898.15) U19.44@4478.66,2898.15
  Bottom Layer w8: v1(3815,3369) v1(4285.85,2898.15)
ADDR3: U1.136 U2.43 U19.43 | length 2026.5
  Top Layer w8: U1.136@3520.59,3207.09 3612.9,3207.09 v1(3848,3442.19) 3938,3532.19 3938,3532.84 4149,3743.84 4149,3901.85 4145.52,3905.33 4145.52,3917.75 4166,3938.23 4166,3959.77 4156.54,3969.23 U2.43@4156.54,4018.66 ; v1(4330,2925) 4334.39,2920.61 4475.88,2920.61 U19.43@4478.66,2917.84
  Top Layer w10: U2.43@4156.54,4023.22 U2.43@4158.31,4025
  Bottom Layer w8: v1(3848,3442.19) 3848,3380.23 4303.23,2925 v1(4330,2925)
ADDR4: U1.137 U2.41 U19.41 | length 2015.1
  Top Layer w10: U1.137@3520.59,3226.77 3522.37,3228.55 3596.47,3228.55 3776,3408.08 3776,3409.18 v1(3851.82,3485) 3889.82,3523 3906.18,3523 3922,3538.82 3922,3539.47 4132,3749.47 4132,3857.77 4133,3858.77 4133,3895.23 4128,3900.23 4128,3922.82 4113,3937.82 4113,3960.18 4122,3969.18 4122,3976.69 4118.94,3979.75 4118.94,4016.88 U2.41@4117.17,4018.66 ; v1(4307.8,2957.21) 4308,2957 4478.46,2957 U19.41@4478.66,2957.21
  Bottom Layer w10: v1(3851.82,3485) 3870,3485 3870,3458.37 3875,3453.37 3875,3431.01 3870,3426.01 3870,3395 v1(4307.8,2957.21)
ADDR5: U1.138 U2.40 U19.40 | length 1984.3
  Top Layer w10: U1.138@3520.59,3246.46 3522.37,3248.24 3592.11,3248.24 3759,3415.13 3759,3430.37 3840.63,3512 3854.77,3512 v1@3893.89,3551.11 ; v1(3895,3550) 3910,3565 3910,3567.23 4115,3772.23 4115,3864.82 4116,3865.82 4116,3888.18 4111,3893.18 4111,3915.77 4096,3930.77 4096,3967.23 4101.94,3973.17 4101.94,3977.06 4099.26,3979.75 4099.26,4016.88 U2.40@4097.48,4018.66 ; v1(4335,2984) 4340.33,2978.67 4476.88,2978.67 U19.40@4478.66,2976.89
  Bottom Layer w10: v1(3895,3550) 3895,3498.18 3897,3496.18 3897,3408 4321,2984 v1(4335,2984)
ADDR6: U1.139 U2.38 U19.38 | length 1937.8
  Top Layer w8: U1.139@3520.59,3266.14 3523.37,3268.92 3578.86,3268.92 3641.82,3331.88 3641.82,3340.05 4062,3760.23 4062,3979.05 4060.89,3980.16 4060.89,4015.88 U2.38@4058.11,4018.66 ; v1@3912,3609 v1(3913,3609) ; v1(4340.67,3022) 4343.63,3019.04 4475.88,3019.04 U19.38@4478.66,3016.26
  Bottom Layer w8: v1(3913,3609) 3928,3594 3928,3424 4340.67,3011.33 v1(4340.67,3022)
ADDR7: U1.140 U2.37 U19.37 | length 1932.2
  Top Layer w8: U1.140@3520.59,3285.83 3523.37,3288.61 3577.33,3288.61 3626.82,3338.1 3626.82,3353.43 3643.82,3370.43 3643.82,3371.03 3887,3614.21 3887,3619.77 3902.23,3635 3907.79,3635 3961,3688.21 3961,3718.02 4047,3804.02 4047,3972.84 4041.2,3978.64 4041.2,4015.88 U2.37@4038.43,4018.66
  Top Layer w10: v1(4365,3050) 4380.96,3050 4393.23,3037.72 4476.88,3037.72 U19.37@4478.66,3035.95
  Bottom Layer w10: v1(3950,3685) 3950,3436.82 4323.82,3063 4332,3063 4345,3050 v1(4365,3050)
ADDR8: U1.141 U2.36 U19.36 | length 1934.5
  Top Layer w8: U1.141@3520.59,3305.51 3523.37,3308.29 3575.8,3308.29 3611.82,3344.31 3611.82,3359.64 3628.82,3376.64 3628.82,3377.24 3696.82,3445.24 3696.82,3481.74 3954.08,3739 3960.77,3739 4032,3810.23 4032,3966.63 4026.2,3972.42 4026.2,3974.68 4018.74,3982.15 U2.36@4018.74,4018.66 ; v1(4337.67,3090) 4404.22,3090 4435.81,3058.41 4475.88,3058.41 U19.36@4478.66,3055.63
  Bottom Layer w8: v1(3925,3714) 3957.77,3714 3976,3695.77 3976,3451.67 v1(4337.67,3090)
ADDR9: U1.142 U2.35 U19.35 | length 1905.7
  Top Layer w8: U1.142@3520.59,3325.2 3520.59,3327.98 3574.27,3327.98 3596.82,3350.52 3596.82,3365.85 3613.82,3382.85 3613.82,3383.46 3681.82,3451.46 3681.82,3496.82 3899,3714 3899,3724.77 3914.23,3740 3925,3740 v1(3950,3765) 4017,3832 4017,3960.41 4011.2,3966.21 4011.2,3968.47 3999.06,3980.62 U2.35@3999.06,4018.66
  Top Layer w10: U2.35@3999.06,4033.22 U2.35@4000.83,4035 ; v1(4360,3120) 4360,3110 4364,3106 4410.84,3106 4439.75,3077.09 4478.66,3077.09 U19.35@4478.66,3075.32
  Bottom Layer w10: v1(3950,3765) 3995,3720 3995,3485 v1(4360,3120)
ADDR10: U1.143 U2.33 U21.47 | length 2013.5
  Top Layer w10: U1.143@3520.59,3344.88 3522.37,3346.66 3570.33,3346.66 3580.82,3357.15 3580.82,3372.48 3597.82,3389.48 3597.82,3390.09 3665.82,3458.09 3665.82,3503.45 3883,3720.63 3883,3731.4 3907.6,3756 3918.37,3756 3923,3760.63 3923,3776.18 3964,3817.18 3964,3966.23 3959.69,3970.54 U2.33@3959.69,4018.66 3959.69,4065.58 3962.1,4068 3971.89,4068 3971.95,4068.06 3986.79,4068.06 3986.85,4068 3991.57,4068 3991.64,4068.06 4006.47,4068.06 4006.54,4068 4011.26,4068 4011.32,4068.06 4026.16,4068.06 4026.22,4068 4030.94,4068 4031.01,4068.06 4045.84,4068.06 4045.91,4068 4050.63,4068 4050.69,4068.06 4065.53,4068.06 4065.59,4068 4070.31,4068 4070.38,4068.06 4085.21,4068.06 4085.28,4068 4090,4068 4090.06,4068.06 4104.9,4068.06 4104.96,4068 4109.68,4068 4109.75,4068.06 4124.58,4068.06 4124.65,4068 4129.37,4068 4129.43,4068.06 4144.27,4068.06 4144.33,4068 4149.05,4068 4149.12,4068.06 4163.95,4068.06 4164.02,4068 4168.74,4068 4168.8,4068.06 4183.64,4068.06 4183.7,4068 4188.42,4068 4188.49,4068.06 4203.32,4068.06 4203.39,4068 4208.11,4068 4208.17,4068.06 4223.01,4068.06 4223.07,4068 4227.79,4068 4227.86,4068.06 4242.69,4068.06 4242.76,4068 4247.48,4068 4247.54,4068.06 4262.38,4068.06 4282,4048.44 4282,3905.13 4272.87,3896 4272.87,3569.05 4380.73,3461.19 4483.22,3461.19 U21.47@4485,3459.41
ADDR11: U1.145 U2.32 U21.46 | length 1989.3
  Top Layer w10: U1.145@3520.59,3384.25 3522.37,3386.03 3570.33,3386.03 3580.82,3396.52 3580.82,3397.13 3648.82,3465.13 3648.82,3510.49 3866,3727.67 3866,3738.44 3906,3778.44 3906,3783.23 3947,3824.23 3947,3959.18 3940,3966.18 U2.32@3940,4018.66 3940,4069.94 3955.06,4085 3964.85,4085 3964.91,4085.06 4269.42,4085.06 4299,4055.48 4299,3888.13 4289.87,3879 4289.87,3576.09 4385.08,3480.87 4483.22,3480.87 U21.46@4485,3479.1
ADDR12: U1.148 U2.30 U21.44 | length 1956
  Top Layer w10: U1.148@3520.59,3443.31 3522.37,3445.09 3583.4,3445.09 3631.82,3493.51 3631.82,3517.53 3849,3734.71 3849,3745.48 3889,3785.48 3889,3790.27 3899,3800.27 3899,3930.82 3893,3936.82 3893,3959.18 3898.85,3965.03 3898.85,4020.44 U2.30@3900.63,4018.66 3900.63,4065.58 3935.05,4100 3942.47,4100 3944.47,4102 3957.81,4102 3957.87,4102.06 4276.46,4102.06 4316,4062.52 4316,3879.73 4306.87,3870.6 4306.87,3588.13 4376.54,3518.47 U21.44@4485,3518.47
ADDR13: U1.149 U2.29 U21.43 | length 1951.6
  Top Layer w10: U1.149@3520.59,3462.99 3522.37,3464.77 3579.04,3464.77 3614.82,3500.55 3614.82,3524.57 3832,3741.75 3832,3752.52 3872,3792.52 3872,3797.31 3882,3807.31 3882,3923.77 3876,3929.77 3876,3966.23 3879.17,3969.39 U2.29@3879.17,4020.44 ; U2.29@3880.95,4018.66 U2.29@3879.17,4020.44 ; U21.43@4485,3538.15 4483.22,3539.93 4381.03,3539.93 4323.87,3597.09 4323.87,3863.56 4333,3872.69 4333,4069.57 4283.5,4119.06 3950.83,4119.06 3950.77,4119 3937.43,4119 3935.43,4117 3928.01,4117 3879.17,4068.16 U2.29@3879.17,4020.44
ADDR14: U1.150 U2.27 U21.41 | length 1983
  Top Layer w10: U1.150@3520.59,3482.68 3522.37,3484.46 3574.68,3484.46 3597.82,3507.59 3597.82,3531.61 3815,3748.79 3815,3759.56 3843.35,3787.92 3843.35,3885.46 3828,3900.82 3828,3923.18 3842,3937.18 3842,3979.23 3839.8,3981.43 3839.8,4019.82 U2.27@3841.58,4021.6 ; U2.27@3841.58,4018.66 U2.27@3841.58,4021.6 ; U21.41@4485,3577.52 4367.48,3577.52 4340.87,3604.13 4340.87,3856.52 4350,3865.65 4350,4076.61 4290.54,4136.06 3943.79,4136.06 3943.72,4136 3930.39,4136 3928.39,4134 3878.04,4134 3841.58,4097.53 U2.27@3841.58,4023.22 ; U2.27@3841.58,4021.6 U2.27@3841.58,4023.22 ; U2.27@3841.58,4021.6 3843.35,4023.38 3843.35,4025 U2.27@3841.58,4023.22
ADDR15: U1.151 U2.26 U21.40 | length 1926.1
  Top Layer w10: U1.151@3520.59,3502.36 3522.37,3504.14 3570.33,3504.14 3580.82,3514.63 3580.82,3538.65 3798,3755.84 3798,3766.6 3820.11,3788.72 3820.11,3884.66 3811,3893.77 3811,3930.23 3825,3944.23 3825,3972.18 3820.11,3977.07 U2.26@3820.11,4020 ; U2.26@3821.89,4018.66 3821.45,4018.66 U2.26@3820.11,4020 ; U21.40@4485,3597.21 4483.22,3598.98 4446.09,3598.98 4357.87,3687.21 4357.87,3849.47 4367,3858.61 4367,4083.65 4297.58,4153.06 3936.75,4153.06 3936.68,4153 3923.35,4153 3921.35,4151 3871,4151 3820.11,4100.11 U2.26@3820.11,4020
ADDR16: U1.154 U8.41 U21.38 | length 2104.9
  Top Layer w10: U1.154@3520.59,3561.42 3522.37,3563.2 3574.68,3563.2 3597.82,3586.33 3597.82,3615.25 3528.74,3684.32 U8.41@3528.74,4020 3528.74,4073.51 3534,4078.77 3534,4115.23 3532,4117.23 3532,4140.18 3561.82,4170 3847.69,4170 3849.69,4168 3914.31,4168 3916.31,4170 3929.64,4170 3929.7,4170.06 4304.63,4170.06 4384,4090.69 4384,3851.57 4374.87,3842.43 4374.87,3696.51 4433.02,3638.35 4483.22,3638.35 U21.38@4485,3636.58
ADDR17: U1.155 U8.40 U21.37 | length 2108.4
  Top Layer w10: U1.155@3520.59,3581.1 3522.37,3582.88 3570.33,3582.88 3580.82,3593.37 3580.82,3608.2 3510.83,3678.19 3510.83,4021.78 U8.40@3509.06,4020 3509.06,4077.87 3517,4085.82 3517,4108.18 3515,4110.18 3515,4147.23 3554.77,4187 3854.73,4187 3856.73,4185 3907.27,4185 3909.27,4187 3922.6,4187 3922.66,4187.06 4311.67,4187.06 4401,4097.73 4401,3844.53 4391.87,3835.39 4391.87,3703.55 4437.37,3658.04 4483.22,3658.04 U21.37@4485,3656.26
ADDR18: U1.156 U8.38 U21.36 | length 2065.9
  Top Layer w10: U1.156@3520.59,3600.79 3469.69,3651.69 U8.38@3469.69,4020 3469.69,4079.13 3463,4085.82 3463,4123 3544,4204 3618.67,4204 3618.73,4204.06 3861.71,4204.06 3863.77,4202 3900.23,4202 3902.29,4204.06 4318.71,4204.06 4418,4104.77 4418,3837.48 4408.87,3828.35 4408.87,3710.59 4441.73,3677.72 4483.22,3677.72 U21.36@4485,3675.95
